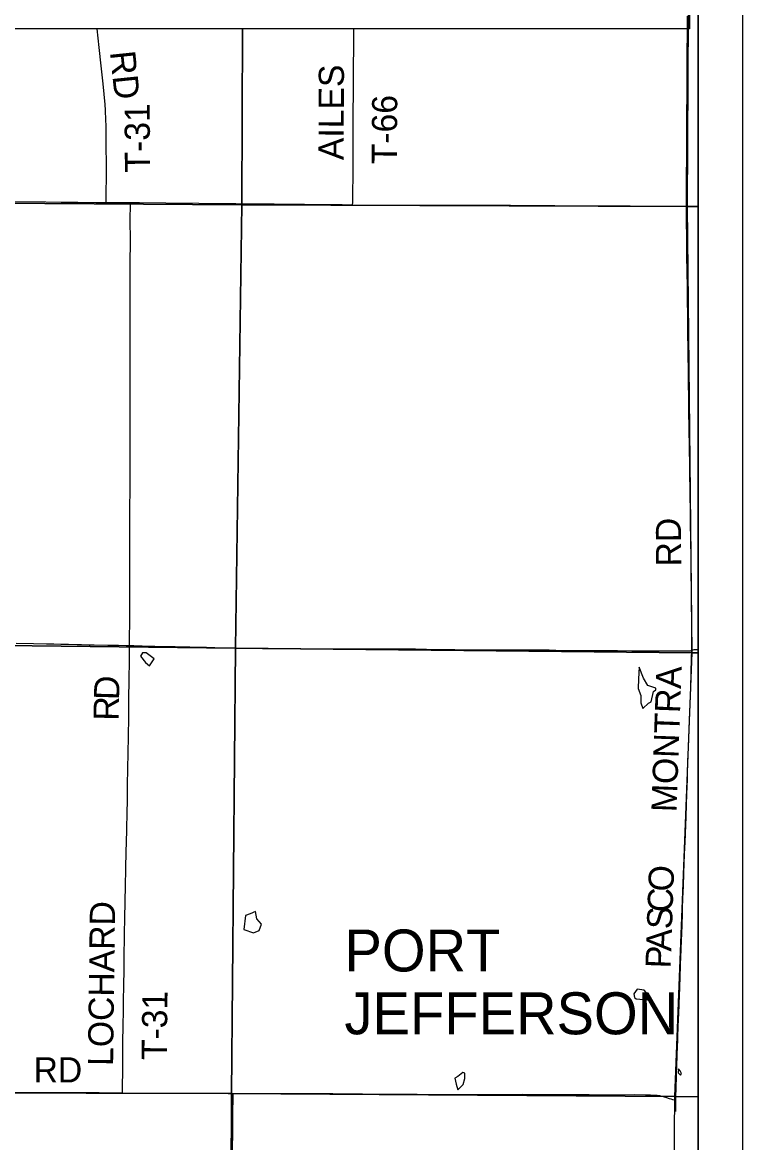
# Model space of a CAD drawing. Extents: x -784 to 1375, y -225 to 440.
# Drawn here: x 549.7 to 582.2, y 311.4 to 362 of the extents above; entities that cross this region are included whole.
import ezdxf

# ---------------------------------------------------------------- set-up
doc = ezdxf.new("R2010")
doc.units = 0
for name, color, linetype in [('GM_X_Corporation_Text', 7, 'Continuous'), ('GM_X_County_Road', 7, 'Continuous'), ('GM_X_County_Road_Text', 7, 'Continuous'), ('GM_X_Minor_Lake', 7, 'Continuous'), ('GM_X_Section', 7, 'Continuous'), ('GM_X_Township', 7, 'Continuous'), ('GM_X_Township_Road', 7, 'Continuous'), ('GM_X_Township_Road_Text', 7, 'Continuous'), ('GM_X_Township_Subdivision', 7, 'Continuous'), ('SH_Data', 7, 'Continuous'), ('SH_Text', 7, 'Continuous')]:
    doc.layers.add(name, color=color, linetype=linetype)

msp = doc.modelspace()

# ---------------------------------------------------------------- linework, layer by layer
at = {"layer": 'GM_X_County_Road'}
for points in [[(579.707, 353.677), (579.707, 354.425), (579.708, 354.699), (579.711, 355.233), (579.715, 355.643), (579.717, 356.066), (579.718, 356.674), (579.72, 356.885), (579.722, 357.283), (579.724, 357.717), (579.726, 358.065), (579.728, 358.488), (579.732, 358.96), (579.738, 359.73), (579.738, 360.19), (579.739, 360.674), (579.744, 361.408), (579.752, 361.892), (579.753, 362.252)], [(539.584, 353.948), (540.879, 353.942), (541.737, 353.937), (542.843, 353.924), (543.986, 353.919), (545.713, 353.908), (547.453, 353.895), (548.049, 353.891), (549.292, 353.884), (550.795, 353.866), (551.491, 353.86), (552.249, 353.851), (553.057, 353.845), (553.526, 353.843)], [(553.526, 353.843), (553.803, 353.841), (554.617, 353.836)], [(554.617, 353.836), (555.033, 353.833), (556.213, 353.821), (557.705, 353.809), (559.37, 353.792), (561.109, 353.777), (561.917, 353.768), (562.464, 353.761), (564.178, 353.743), (564.644, 353.736)], [(564.644, 353.736), (566.763, 353.726), (567.26, 353.725), (567.819, 353.724), (569.41, 353.723), (570.23, 353.723), (570.69, 353.719), (571.758, 353.712), (572.74, 353.706), (573.212, 353.704), (573.772, 353.703), (575.747, 353.69), (576.406, 353.686), (577.164, 353.682), (578.53, 353.681), (579.624, 353.677), (579.707, 353.677)], [(579.945, 333.642), (579.946, 333.678), (579.952, 334.287), (579.946, 335.082), (579.938, 335.628), (579.93, 336.237), (579.925, 336.585), (579.921, 336.895), (579.917, 337.293), (579.91, 337.852), (579.904, 338.561), (579.903, 338.784), (579.892, 339.231), (579.884, 339.616), (579.879, 339.964), (579.872, 340.598), (579.866, 341.095), (579.862, 341.381), (579.86, 341.791), (579.852, 342.163), (579.844, 342.586), (579.841, 343.045), (579.832, 343.381), (579.822, 343.815), (579.813, 344.275), (579.808, 344.647), (579.805, 345.095), (579.798, 345.629), (579.795, 346.002), (579.788, 346.449), (579.784, 346.772), (579.78, 347.157), (579.776, 347.455), (579.772, 347.741), (579.769, 347.964), (579.762, 348.747), (579.755, 349.456), (579.75, 349.953), (579.745, 350.276), (579.741, 350.462), (579.734, 350.847), (579.727, 351.306), (579.721, 351.779), (579.719, 352.065), (579.715, 352.474), (579.712, 352.785), (579.71, 352.934), (579.707, 353.444), (579.707, 353.677)], [(579.707, 353.677), (580.236, 353.675)], [(579.435, 319.477), (579.447, 319.775), (579.458, 320.135), (579.477, 320.557), (579.488, 320.83), (579.504, 321.264), (579.519, 321.723), (579.529, 322.033), (579.543, 322.418), (579.556, 322.741), (579.565, 322.989), (579.591, 323.584), (579.62, 324.44), (579.643, 324.986), (579.689, 326.128), (579.707, 326.687), (579.722, 327.146), (579.745, 327.804), (579.753, 328.077), (579.772, 328.636), (579.79, 329.232), (579.823, 330.101), (579.851, 330.859), (579.878, 331.567), (579.895, 331.964), (579.936, 333.268), (579.945, 333.642)], [(579.354, 317.218), (579.373, 317.677), (579.388, 318.074), (579.401, 318.41), (579.419, 318.919), (579.432, 319.378), (579.435, 319.477)], [(579.231, 313.538), (579.235, 313.835), (579.254, 314.479), (579.27, 314.9), (579.286, 315.358), (579.303, 315.802), (579.31, 316.024), (579.316, 316.236), (579.329, 316.621), (579.344, 317.013)], [(579.344, 317.013), (579.354, 317.218)], [(579.22, 312.829), (579.228, 313.274), (579.228, 313.338)], [(579.228, 313.338), (579.231, 313.538)]]:
    msp.add_lwpolyline(points, dxfattribs=at)
at = {"layer": 'GM_X_Minor_Lake'}
msp.add_line((579.436, 314.468), (579.482, 314.546), dxfattribs=at)
for points in [[(555.683, 333.258), (555.324, 333.519), (555.165, 333.523), (555.07, 333.38)], [(555.07, 333.38), (555.298, 333.093), (555.477, 332.944), (555.683, 333.258), (555.324, 333.519), (555.165, 333.523), (555.07, 333.38)], [(555.07, 333.38), (555.298, 333.093), (555.477, 332.944), (555.683, 333.258)], [(577.568, 332.88), (577.543, 332.356), (577.524, 331.915), (577.646, 331.6), (577.645, 331.265), (577.737, 331.012)], [(577.737, 331.012), (577.987, 331.257), (578.118, 331.322), (578.221, 331.776), (578.314, 331.857), (578.316, 331.926), (577.961, 332.049), (577.772, 332.381), (577.568, 332.88)], [(559.814, 321.677), (559.729, 321.04), (560.167, 320.899), (560.423, 320.992)], [(560.423, 320.992), (560.526, 321.278), (560.327, 321.519), (560.267, 321.856), (560.021, 321.755), (559.814, 321.677)], [(577.481, 318.355), (577.323, 318.137), (577.365, 317.976), (577.439, 317.913), (577.941, 317.869)], [(577.941, 317.869), (577.984, 318.082), (577.8, 318.315), (577.481, 318.355)], [(569.392, 314.414), (569.259, 314.336), (569.313, 314.061), (569.39, 313.808)], [(569.39, 313.808), (569.625, 314.053), (569.708, 314.325), (569.707, 314.569), (569.608, 314.594), (569.392, 314.414)], [(579.35, 314.765), (579.333, 314.584), (579.436, 314.468)], [(579.482, 314.546), (579.426, 314.673), (579.35, 314.765)]]:
    msp.add_lwpolyline(points, dxfattribs=at)
at = {"layer": 'GM_X_Section'}
for p, q in [((580.236, 353.654), (580.236, 373.815)), ((580.236, 333.52), (580.236, 353.654)), ((580.236, 313.496), (580.236, 333.52)), ((580.236, 307.348), (580.236, 313.496))]:
    msp.add_line(p, q, dxfattribs=at)
for points in [[(559.72, 373.821), (559.72, 373.843), (579.839, 373.821), (579.739, 353.659), (559.644, 353.735), (559.674, 361.675)], [(580.236, 373.815), (579.839, 373.821), (579.739, 353.659), (580.236, 353.654)], [(559.674, 361.675), (559.644, 353.735), (539.64, 353.876), (539.743, 361.675)], [(580.236, 353.654), (579.739, 353.659), (579.942, 333.522), (580.236, 333.52)], [(580.236, 333.52), (579.942, 333.522), (579.171, 313.507), (580.236, 313.496)], [(559.1, 293.569), (559.175, 313.642), (579.171, 313.507), (579.102, 306.948)], [(580.236, 313.496), (579.171, 313.507), (579.102, 306.948), (579.216, 306.977), (579.369, 307.019), (579.643, 307.106), (579.811, 307.171), (579.948, 307.222), (580.093, 307.287), (580.236, 307.348)]]:
    msp.add_lwpolyline(points, dxfattribs=at)
for points in [[(559.644, 353.735), (559.365, 333.735), (539.683, 333.96), (539.64, 353.876)], [(579.739, 353.659), (579.942, 333.522), (559.365, 333.735), (559.644, 353.735)], [(539.683, 333.96), (559.365, 333.735), (559.175, 313.642), (539.515, 313.692)], [(559.365, 333.735), (579.942, 333.522), (579.171, 313.507), (559.175, 313.642)], [(539.515, 313.692), (559.175, 313.642), (559.1, 293.569), (539.382, 293.628)]]:
    msp.add_lwpolyline(points, close=True, dxfattribs=at)
at = {"layer": 'GM_X_Township'}
msp.add_lwpolyline([(580.236, 307.641), (580.236, 381.078)], dxfattribs=at)
at = {"layer": 'GM_X_Township_Road'}
for points in [[(553.526, 353.843), (553.526, 353.978), (553.535, 355.295), (553.53, 356.65), (553.522, 357.308), (553.516, 357.557), (553.499, 358.003), (553.482, 358.264), (553.437, 358.721), (553.389, 359.19), (553.303, 360.006), (553.213, 360.834), (553.122, 361.675)], [(564.644, 353.736), (564.646, 353.841), (564.655, 354.301), (564.661, 355.022), (564.669, 356.24), (564.668, 356.948), (564.674, 357.644), (564.679, 359.048), (564.685, 360.08), (564.691, 360.726), (564.696, 361.496), (564.697, 361.675)], [(554.582, 333.855), (554.579, 334.2), (554.585, 334.921), (554.587, 335.418), (554.589, 335.679), (554.59, 337.057), (554.591, 338.15), (554.594, 338.696), (554.59, 339.305), (554.593, 339.852), (554.601, 341.082), (554.601, 341.653), (554.602, 342.846), (554.603, 344.325), (554.603, 345.567), (554.602, 346.561), (554.603, 347.257), (554.608, 347.84), (554.603, 349.145), (554.607, 349.865), (554.608, 350.449), (554.608, 351.083), (554.616, 352.102), (554.614, 353.083), (554.616, 353.717), (554.617, 353.836)], [(549.471, 333.967), (550.241, 333.952), (550.825, 333.935), (551.16, 333.928), (551.483, 333.923), (551.818, 333.914), (552.215, 333.904), (552.414, 333.9), (552.762, 333.893), (552.985, 333.891), (553.605, 333.878), (554.077, 333.867), (554.425, 333.858), (554.582, 333.855)], [(554.259, 313.673), (554.261, 313.817), (554.276, 314.823), (554.281, 315.146), (554.283, 315.544), (554.283, 315.954), (554.296, 316.711), (554.308, 317.382), (554.313, 317.842), (554.324, 318.5), (554.335, 319.245), (554.339, 319.705), (554.339, 320.077), (554.347, 320.474), (554.355, 320.884), (554.369, 321.542), (554.379, 322.3), (554.392, 323.008), (554.405, 323.766), (554.43, 324.586), (554.44, 324.946), (554.455, 325.592), (554.473, 326.3), (554.483, 326.871), (554.492, 327.567), (554.506, 328.288), (554.528, 329.729), (554.541, 330.636), (554.55, 331.518), (554.56, 332.226), (554.581, 333.256), (554.584, 333.678), (554.582, 333.855)], [(554.582, 333.855), (554.773, 333.851), (555.146, 333.847), (555.717, 333.832), (556.238, 333.816), (556.636, 333.808), (557.294, 333.793), (558.052, 333.778), (558.798, 333.758), (559.046, 333.754), (559.357, 333.749), (559.941, 333.736), (560.574, 333.726), (560.91, 333.722), (561.196, 333.72), (562.289, 333.712), (562.575, 333.711), (563.084, 333.708), (563.818, 333.706), (564.737, 333.709), (565.57, 333.706), (566.576, 333.7), (567.484, 333.698), (567.657, 333.695), (567.98, 333.688), (568.415, 333.682), (568.812, 333.679), (569.247, 333.674), (569.856, 333.667), (570.763, 333.66), (571.223, 333.66), (571.534, 333.658), (571.907, 333.661), (572.676, 333.659), (573.198, 333.653), (573.508, 333.654), (573.805, 333.646), (574.948, 333.636), (575.407, 333.63), (576.187, 333.63), (576.596, 333.626), (577.24, 333.622), (577.712, 333.622), (578.144, 333.62), (578.673, 333.613), (579.232, 333.613), (579.803, 333.609), (579.848, 333.614), (579.885, 333.622), (579.945, 333.642)], [(539.431, 313.71), (539.717, 313.707), (540.093, 313.703), (541.777, 313.711), (542.447, 313.71), (543.18, 313.712), (544.41, 313.712), (545.031, 313.71), (545.64, 313.711), (546.299, 313.712), (547.492, 313.711), (547.777, 313.71), (548.709, 313.702), (549.243, 313.703), (550.262, 313.697), (551.045, 313.694), (552.212, 313.692), (553.206, 313.689), (553.802, 313.68), (554.259, 313.673)], [(554.259, 313.673), (555.045, 313.662), (556.424, 313.66), (557.17, 313.661), (558.512, 313.654), (559.034, 313.651), (559.251, 313.65)], [(559.18, 302.27), (559.188, 302.974), (559.191, 303.583), (559.193, 303.993), (559.2, 304.664), (559.202, 305.148), (559.202, 305.782), (559.198, 306.577), (559.2, 307.297), (559.201, 308.13), (559.207, 308.875), (559.209, 309.422), (559.217, 310.192), (559.222, 310.689), (559.223, 310.95), (559.228, 311.335), (559.232, 311.708), (559.238, 312.254), (559.24, 312.702), (559.25, 313.547), (559.251, 313.65)], [(559.251, 313.65), (560.301, 313.653), (561.221, 313.652), (562.663, 313.652), (563.619, 313.643), (563.743, 313.642), (564.427, 313.638), (565.085, 313.634), (566.774, 313.623), (567.557, 313.618), (568.962, 313.598), (570.151, 313.601), (571.033, 313.604), (571.368, 313.605), (572.309, 313.612), (573.649, 313.598), (574.345, 313.594), (575.313, 313.594), (576.567, 313.591), (577.362, 313.594), (577.859, 313.588), (578.082, 313.585), (578.244, 313.578), (578.379, 313.567), (578.489, 313.55), (578.574, 313.532), (578.657, 313.509), (578.798, 313.465), (578.925, 313.422), (578.996, 313.4), (579.067, 313.38), (579.146, 313.36), (579.228, 313.338)]]:
    msp.add_lwpolyline(points, dxfattribs=at)
at = {"layer": 'GM_X_Township_Subdivision'}
msp.add_lwpolyline([(579.945, 333.642), (580, 333.663), (580.053, 333.673), (580.092, 333.675), (580.236, 333.673)], dxfattribs=at)
at = {"layer": 'SH_Data'}
for p, q in [((582.236, 421.309), (582.236, 281.309)), ((580.236, 419.309), (580.236, 283.309))]:
    msp.add_line(p, q, dxfattribs=at)
at = {"layer": 'SH_Text'}
msp.add_lwpolyline([(532.832, 373.821), (579.839, 373.821), (579.839, 361.675), (532.832, 361.675)], close=True, dxfattribs=at)

# ---------------------------------------------------------------- texts
at = {"layer": 'GM_X_Corporation_Text'}
for s, p in [('PORT', (564.275, 319.15)), ('JEFFERSON', (564.275, 316.317))]:
    msp.add_text(s, height=1.8939, rotation=0, dxfattribs=at).set_placement(p)
at = {"layer": 'GM_X_County_Road_Text'}
for s, height, rotation, p in [('RD', 1.1364, 90.4716, (579.47, 337.427)), ('MONTRA', 1.1364, 87.9611, (579.253, 326.325)), ('O', 1.136, 87.544, (579.107, 322.742)), ('C', 1.136, 88.0013, (579.074, 321.812)), ('S', 1.136, 88.0075, (579.048, 321.046)), ('A', 1.136, 88.009, (579.013, 320.046)), ('P', 1.136, 88.0087, (578.986, 319.28))]:
    msp.add_text(s, height=height, rotation=rotation, dxfattribs=at).set_placement(p)
at = {"layer": 'GM_X_Township_Road_Text'}
for s, height, rotation, p in [('RD', 1.1364, 275.9066, (553.694, 360.627)), ('AILES', 1.1364, 89.7589, (564.236, 355.75)), ('T-66', 1.1364, 89.6552, (566.639, 355.563)), ('T-31', 1.1364, 90.3528, (555.506, 355.195)), ('D', 1.136, 88.4334, (554.104, 331.387)), ('R', 1.136, 88.9266, (554.087, 330.456)), ('LOCHARD', 1.1364, 89.2883, (553.836, 314.886)), ('T-31', 1.1364, 89.3119, (556.256, 315.148)), ('RD', 1.1364, 0, (550.25, 314.145))]:
    msp.add_text(s, height=height, rotation=rotation, dxfattribs=at).set_placement(p)

doc.saveas('drawing.dxf')
